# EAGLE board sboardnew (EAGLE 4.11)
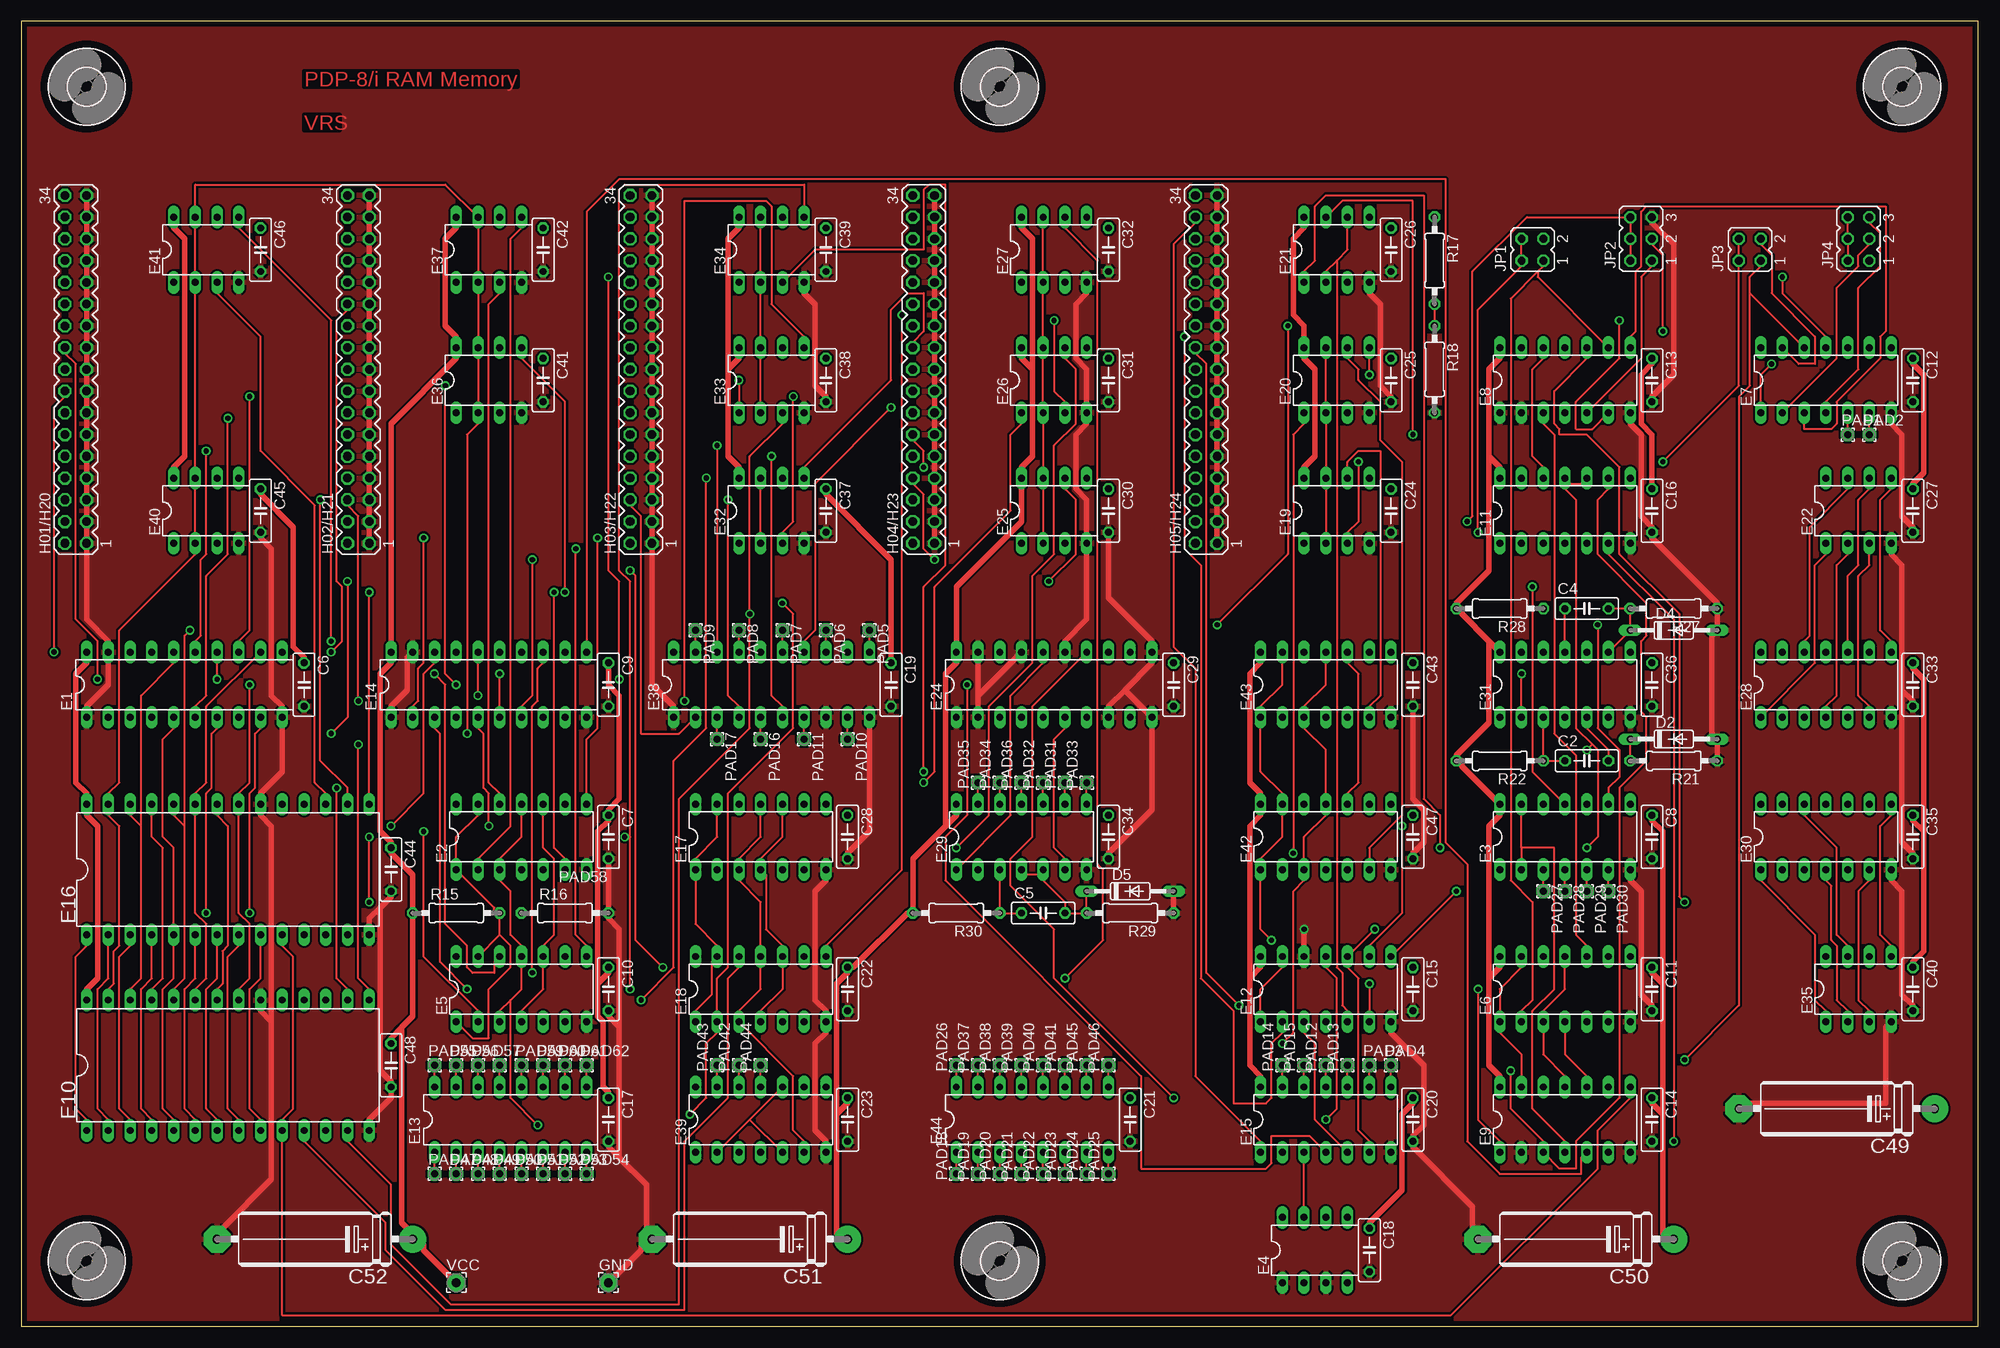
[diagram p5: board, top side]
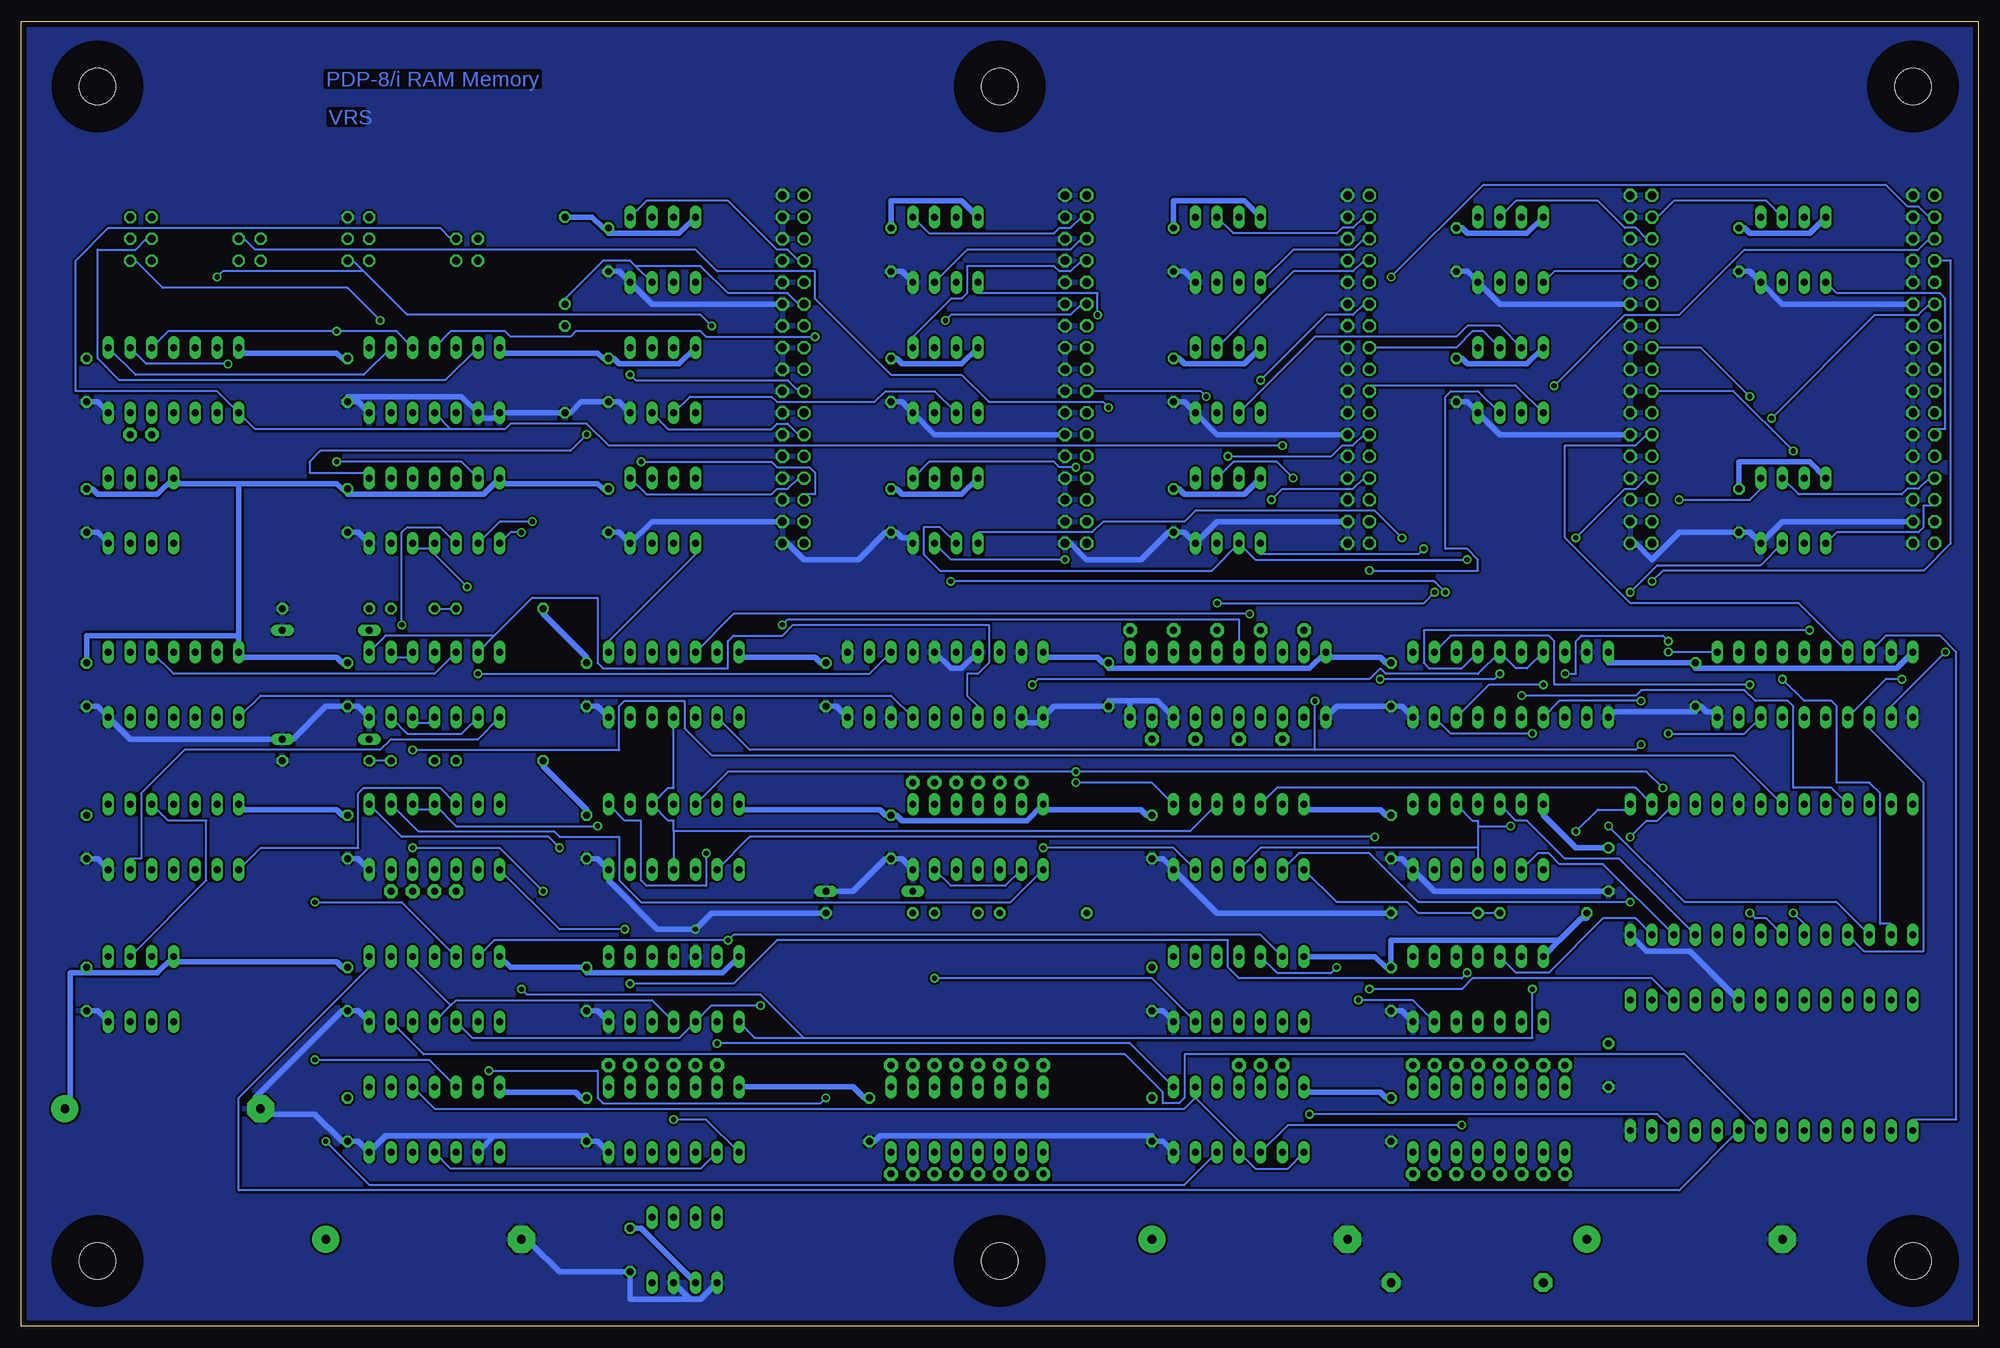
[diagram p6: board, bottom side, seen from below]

Size 228.6 x 152.4 mm. Coordinates in mm from the lower left corner, seen from the top.
Outline: 0,0 228.6,0 228.6,152.4 0,152.4 0,0
Copper layers (1*16): Top 0.035mm / dielectric 1.5mm / Bottom 0.035mm
Design rules "olimex10mil": minimum track width 10mil, minimum drill 24mil, track to track 10mil, track to pad 10mil, pad to pad 10mil, via to via 10mil, smd to smd 10mil, copper to edge 25mil, drill to drill 10mil, minimum pad ring 10mil, minimum via ring 8mil, stop-mask expansion 0mil, vias tented up to drill 0mil, thermal gap 10mil
Net classes: 1 Power: width 0.635 mm

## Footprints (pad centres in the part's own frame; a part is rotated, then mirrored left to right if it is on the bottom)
C050-025X075 = drill 0.813 octagon: 1 -2.54,0; 2 2.54,0
E22-6 = drill 1.016 pad 3.15 round: + -11.43,0 | drill 1.016 pad 3.15 octagon: - 11.43,0
DO35-10 = drill 0.813 long: A 5.08,0; C -5.08,0
DIL20 = drill 0.813 long: 1 -11.43,-3.81; 2 -8.89,-3.81; 3 -6.35,-3.81; 4 -3.81,-3.81; 5 -1.27,-3.81; 6 1.27,-3.81; 7 3.81,-3.81; 8 6.35,-3.81; 9 8.89,-3.81; 10 11.43,-3.81; 11 11.43,3.81; 12 8.89,3.81; 13 6.35,3.81; 14 3.81,3.81; 15 1.27,3.81; 16 -1.27,3.81; 17 -3.81,3.81; 18 -6.35,3.81; 19 -8.89,3.81; 20 -11.43,3.81
DIL14 = drill 0.813 long: 1 -7.62,-3.81; 2 -5.08,-3.81; 3 -2.54,-3.81; 4 0,-3.81; 5 2.54,-3.81; 6 5.08,-3.81; 7 7.62,-3.81; 8 7.62,3.81; 9 5.08,3.81; 10 2.54,3.81; 11 0,3.81; 12 -2.54,3.81; 13 -5.08,3.81; 14 -7.62,3.81
DIL08 = drill 0.813 long: 1 -3.81,-3.81; 2 -1.27,-3.81; 3 1.27,-3.81; 4 3.81,-3.81; 5 3.81,3.81; 6 1.27,3.81; 7 -1.27,3.81; 8 -3.81,3.81
DIL28-6 = drill 0.813 long: 1 -16.51,-7.62; 2 -13.97,-7.62; 3 -11.43,-7.62; 4 -8.89,-7.62; 5 -6.35,-7.62; 6 -3.81,-7.62; 7 -1.27,-7.62; 8 1.27,-7.62; 9 3.81,-7.62; 10 6.35,-7.62; 11 8.89,-7.62; 12 11.43,-7.62; 13 13.97,-7.62; 14 16.51,-7.62; 15 16.51,7.62; 16 13.97,7.62; 17 11.43,7.62; 18 8.89,7.62; 19 6.35,7.62; 20 3.81,7.62; 21 1.27,7.62; 22 -1.27,7.62; 23 -3.81,7.62; 24 -6.35,7.62; 25 -8.89,7.62; 26 -11.43,7.62; 27 -13.97,7.62; 28 -16.51,7.62
DIL16 = drill 0.813 long: 1 -8.89,-3.81; 2 -6.35,-3.81; 3 -3.81,-3.81; 4 -1.27,-3.81; 5 1.27,-3.81; 6 3.81,-3.81; 7 6.35,-3.81; 8 8.89,-3.81; 9 8.89,3.81; 10 6.35,3.81; 11 3.81,3.81; 12 1.27,3.81; 13 -1.27,3.81; 14 -3.81,3.81; 15 -6.35,3.81; 16 -8.89,3.81
2,15/1,0 = drill 1.016 pad 2.159 octagon: 1 0,0
MA17-2 = drill 1.016 octagon: 1 -20.32,-1.27; 2 -20.32,1.27; 3 -17.78,-1.27; 4 -17.78,1.27; 5 -15.24,-1.27; 6 -15.24,1.27; 7 -12.7,-1.27; 8 -12.7,1.27; 9 -10.16,-1.27; 10 -10.16,1.27; 11 -7.62,-1.27; 12 -7.62,1.27; 13 -5.08,-1.27; 14 -5.08,1.27; 15 -2.54,-1.27; 16 -2.54,1.27; 17 0,-1.27; 18 0,1.27; 19 2.54,-1.27; 20 2.54,1.27; 21 5.08,-1.27; 22 5.08,1.27; 23 7.62,-1.27; 24 7.62,1.27; 25 10.16,-1.27; 26 10.16,1.27; 27 12.7,-1.27; 28 12.7,1.27; 29 15.24,-1.27; 30 15.24,1.27; 31 17.78,-1.27; 32 17.78,1.27; 33 20.32,-1.27; 34 20.32,1.27
JP2Q = drill 0.914 octagon: 1 -1.27,-1.27; 2 -1.27,1.27; 3 1.27,-1.27; 4 1.27,1.27
JP3Q = drill 0.914 octagon: 1 -2.54,-1.27; 2 -2.54,1.27; 3 0,-1.27; 4 0,1.27; 5 2.54,-1.27; 6 2.54,1.27
1,6/0,8 = drill 0.813 pad 1.6 octagon: 1 0,0
0207/10 = drill 0.813 octagon: 1 -5.08,0; 2 5.08,0
4,3 = hole 4.3: 0,0

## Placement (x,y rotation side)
C2  .22uf  [C050-025X075]  182.88,66.04 0 top
C4  .22uf  [C050-025X075]  182.88,83.82 0 top
C5  .22uf  [C050-025X075]  119.38,48.26 0 top
C6  [C050-025X075]  33.02,74.93 270 top
C7  [C050-025X075]  68.58,57.15 270 top
C8  [C050-025X075]  190.5,57.15 270 top
C9  [C050-025X075]  68.58,74.93 270 top
C10  [C050-025X075]  68.58,39.37 270 top
C11  [C050-025X075]  190.5,39.37 270 top
C12  [C050-025X075]  220.98,110.49 270 top
C13  [C050-025X075]  190.5,110.49 270 top
C14  [C050-025X075]  190.5,24.13 270 top
C15  [C050-025X075]  162.56,39.37 270 top
C16  [C050-025X075]  190.5,95.25 270 top
C17  [C050-025X075]  68.58,24.13 270 top
C18  [C050-025X075]  157.48,8.89 270 top
C19  [C050-025X075]  101.6,74.93 270 top
C20  [C050-025X075]  162.56,24.13 270 top
C21  [C050-025X075]  129.54,24.13 270 top
C22  [C050-025X075]  96.52,39.37 270 top
C23  [C050-025X075]  96.52,24.13 270 top
C24  [C050-025X075]  160.02,95.25 270 top
C25  [C050-025X075]  160.02,110.49 270 top
C26  [C050-025X075]  160.02,125.73 270 top
C27  [C050-025X075]  220.98,95.25 270 top
C28  [C050-025X075]  96.52,57.15 270 top
C29  [C050-025X075]  134.62,74.93 270 top
C30  [C050-025X075]  127,95.25 270 top
C31  [C050-025X075]  127,110.49 270 top
C32  [C050-025X075]  127,125.73 270 top
C33  [C050-025X075]  220.98,74.93 270 top
C34  [C050-025X075]  127,57.15 270 top
C35  [C050-025X075]  220.98,57.15 270 top
C36  [C050-025X075]  190.5,74.93 270 top
C37  [C050-025X075]  93.98,95.25 270 top
C38  [C050-025X075]  93.98,110.49 270 top
C39  [C050-025X075]  93.98,125.73 270 top
C40  [C050-025X075]  220.98,39.37 270 top
C41  [C050-025X075]  60.96,110.49 270 top
C42  [C050-025X075]  60.96,125.73 270 top
C43  [C050-025X075]  162.56,74.93 270 top
C44  [C050-025X075]  43.18,53.34 270 top
C45  [C050-025X075]  27.94,95.25 270 top
C46  [C050-025X075]  27.94,125.73 270 top
C47  [C050-025X075]  162.56,57.15 270 top
C48  [C050-025X075]  43.18,30.48 270 top
C49  [E22-6]  212.09,25.4 180 top
C50  [E22-6]  181.61,10.16 180 top
C51  [E22-6]  85.09,10.16 180 top
C52  [E22-6]  34.29,10.16 180 top
D2  1N4148  [DO35-10]  193.04,68.58 0 top
D4  1N4148  [DO35-10]  193.04,81.28 0 top
D5  1N4148  [DO35-10]  129.54,50.8 0 top
E1  74S240N  [DIL20]  19.05,74.93 0 top
E2  74S74N  [DIL14]  58.42,57.15 0 top
E3  7410N  [DIL14]  180.34,57.15 0 top
E4  MAX702CPA  [DIL08]  151.13,8.89 0 top
E5  74S74N  [DIL14]  58.42,39.37 0 top
E6  74S74N  [DIL14]  180.34,39.37 0 top
E7  7404N  [DIL14]  210.82,110.49 0 top
E8  7400N  [DIL14]  180.34,110.49 0 top
E9  74S74N  [DIL14]  180.34,24.13 0 top
E10  [DIL28-6]  24.13,30.48 0 top
E11  7410N  [DIL14]  180.34,95.25 0 top
E12  74S74N  [DIL14]  152.4,39.37 0 top
E13  [DIL16]  57.15,24.13 0 top
E14  74S240N  [DIL20]  54.61,74.93 0 top
E15  7404N  [DIL14]  152.4,24.13 0 top
E16  [DIL28-6]  24.13,53.34 0 top
E17  74S74N  [DIL14]  86.36,57.15 0 top
E18  74S74N  [DIL14]  86.36,39.37 0 top
E19  DS75453N  [DIL08]  153.67,95.25 0 top
E20  DS75453N  [DIL08]  153.67,110.49 0 top
E21  DS75453N  [DIL08]  153.67,125.73 0 top
E22  DS1100M-250  [DIL08]  214.63,95.25 0 top
E24  74S240N  [DIL20]  120.65,74.93 0 top
E25  DS75453N  [DIL08]  120.65,95.25 0 top
E26  DS75453N  [DIL08]  120.65,110.49 0 top
E27  DS75453N  [DIL08]  120.65,125.73 0 top
E28  DS1005-250  [DIL14]  210.82,74.93 0 top
E29  7400N  [DIL14]  116.84,57.15 0 top
E30  DS1005-250  [DIL14]  210.82,57.15 0 top
E31  7400N  [DIL14]  180.34,74.93 0 top
E32  DS75453N  [DIL08]  87.63,95.25 0 top
E33  DS75453N  [DIL08]  87.63,110.49 0 top
E34  DS75453N  [DIL08]  87.63,125.73 0 top
E35  DS1100M-250  [DIL08]  214.63,39.37 0 top
E36  DS75453N  [DIL08]  54.61,110.49 0 top
E37  DS75453N  [DIL08]  54.61,125.73 0 top
E38  74S240N  [DIL20]  87.63,74.93 0 top
E39  7400N  [DIL14]  86.36,24.13 0 top
E40  DS75453N  [DIL08]  21.59,95.25 0 top
E41  DS75453N  [DIL08]  21.59,125.73 0 top
E42  74S74N  [DIL14]  152.4,57.15 0 top
E43  74S74N  [DIL14]  152.4,74.93 0 top
E44  [DIL16]  118.11,24.13 0 top
GND  [2,15/1,0]  68.58,5.08 0 top
H01/H20  [MA17-2]  6.35,111.76 90 top
H02/H21  [MA17-2]  39.37,111.76 90 top
H03/H22  [MA17-2]  72.39,111.76 90 top
H04/H23  [MA17-2]  105.41,111.76 90 top
H05/H24  [MA17-2]  138.43,111.76 90 top
JP1  [JP2Q]  176.53,125.73 90 top
JP2  [JP3Q]  189.23,127 90 top
JP3  [JP2Q]  201.93,125.73 90 top
JP4  [JP3Q]  214.63,127 90 top
PAD1  [1,6/0,8]  213.36,104.14 0 top
PAD2  [1,6/0,8]  215.9,104.14 0 top
PAD3  [1,6/0,8]  157.48,30.48 0 top
PAD4  [1,6/0,8]  160.02,30.48 0 top
PAD5  [1,6/0,8]  99.06,81.28 270 top
PAD6  [1,6/0,8]  93.98,81.28 270 top
PAD7  [1,6/0,8]  88.9,81.28 270 top
PAD8  [1,6/0,8]  83.82,81.28 270 top
PAD9  [1,6/0,8]  78.74,81.28 270 top
PAD10  [1,6/0,8]  96.52,68.58 270 top
PAD11  [1,6/0,8]  91.44,68.58 270 top
PAD12  [1,6/0,8]  152.4,30.48 90 top
PAD13  [1,6/0,8]  154.94,30.48 90 top
PAD14  [1,6/0,8]  147.32,30.48 90 top
PAD15  [1,6/0,8]  149.86,30.48 90 top
PAD16  [1,6/0,8]  86.36,68.58 270 top
PAD17  [1,6/0,8]  81.28,68.58 270 top
PAD18  [1,6/0,8]  109.22,17.78 90 top
PAD19  [1,6/0,8]  111.76,17.78 90 top
PAD20  [1,6/0,8]  114.3,17.78 90 top
PAD21  [1,6/0,8]  116.84,17.78 90 top
PAD22  [1,6/0,8]  119.38,17.78 90 top
PAD23  [1,6/0,8]  121.92,17.78 90 top
PAD24  [1,6/0,8]  124.46,17.78 90 top
PAD25  [1,6/0,8]  127,17.78 90 top
PAD26  [1,6/0,8]  109.22,30.48 90 top
PAD27  [1,6/0,8]  177.8,50.8 270 top
PAD28  [1,6/0,8]  180.34,50.8 270 top
PAD29  [1,6/0,8]  182.88,50.8 270 top
PAD30  [1,6/0,8]  185.42,50.8 270 top
PAD31  [1,6/0,8]  121.92,63.5 90 top
PAD32  [1,6/0,8]  119.38,63.5 90 top
PAD33  [1,6/0,8]  124.46,63.5 90 top
PAD34  [1,6/0,8]  114.3,63.5 90 top
PAD35  [1,6/0,8]  111.76,63.5 90 top
PAD36  [1,6/0,8]  116.84,63.5 90 top
PAD37  [1,6/0,8]  111.76,30.48 90 top
PAD38  [1,6/0,8]  114.3,30.48 90 top
PAD39  [1,6/0,8]  116.84,30.48 90 top
PAD40  [1,6/0,8]  119.38,30.48 90 top
PAD41  [1,6/0,8]  121.92,30.48 90 top
PAD42  [1,6/0,8]  83.82,30.48 90 top
PAD43  [1,6/0,8]  81.28,30.48 90 top
PAD44  [1,6/0,8]  86.36,30.48 90 top
PAD45  [1,6/0,8]  124.46,30.48 90 top
PAD46  [1,6/0,8]  127,30.48 90 top
PAD47  [1,6/0,8]  48.26,17.78 0 top
PAD48  [1,6/0,8]  50.8,17.78 0 top
PAD49  [1,6/0,8]  53.34,17.78 0 top
PAD50  [1,6/0,8]  55.88,17.78 0 top
PAD51  [1,6/0,8]  58.42,17.78 0 top
PAD52  [1,6/0,8]  60.96,17.78 0 top
PAD53  [1,6/0,8]  63.5,17.78 0 top
PAD54  [1,6/0,8]  66.04,17.78 0 top
PAD55  [1,6/0,8]  48.26,30.48 0 top
PAD56  [1,6/0,8]  50.8,30.48 0 top
PAD57  [1,6/0,8]  53.34,30.48 0 top
PAD58  [1,6/0,8]  55.88,30.48 0 top
PAD59  [1,6/0,8]  58.42,30.48 0 top
PAD60  [1,6/0,8]  60.96,30.48 0 top
PAD61  [1,6/0,8]  63.5,30.48 0 top
PAD62  [1,6/0,8]  66.04,30.48 0 top
R15  330  [0207/10]  50.8,48.26 0 top
R16  750  [0207/10]  63.5,48.26 0 top
R17  330  [0207/10]  165.1,124.46 270 top
R18  750  [0207/10]  165.1,111.76 270 top
R21  330  [0207/10]  193.04,66.04 180 top
R22  330  [0207/10]  172.72,66.04 180 top
R27  330  [0207/10]  193.04,83.82 180 top
R28  330  [0207/10]  172.72,83.82 180 top
R29  330  [0207/10]  129.54,48.26 180 top
R30  330  [0207/10]  109.22,48.26 180 top
U$20  [4,3]  219.71,144.78 270 top
U$66  [4,3]  114.3,144.78 270 top
U$67  [4,3]  114.3,7.62 270 top
U$82  [4,3]  219.71,7.62 270 top
U$83  [4,3]  7.62,7.62 270 top
U$86  [4,3]  7.62,144.78 270 top
VCC  [2,15/1,0]  50.8,5.08 0 top

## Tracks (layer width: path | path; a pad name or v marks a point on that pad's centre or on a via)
B17S1
  Top 0.254: E9.10 182.88,29.21 180.34,31.75 E6.4 | E8.3 177.8,105.41 179.07,104.14 179.07,69.22 181.61,66.67 181.61,45.72 182.88,44.45 E6.10
  Bottom 0.254: E39.1 80.64,18.41 84.45,18.41 E39.4 86.36,21.59 91.44,26.67 | 178.44,37.47 177.8,38.1 154.94,38.1 E12.4 | 178.44,37.47 E6.4 | 178.44,37.47 182.88,41.91 E6.10 | 91.44,26.67 92.71,25.4 180.34,25.4 E9.10 | 91.44,26.67 E39.9
B17V1  (via drill 0.61)
  Top 0.254: E18.1 78.74,36.83 80.64,38.73 80.64,42.55 E18.13 81.28,44.45 78.74,46.99 E17.1 78.74,54.61 81.28,57.15 E17.13 | 55.88,45.72 57.15,44.45 57.15,41.91 54.61,39.37 54.61,33.66 52.7,33.66 E5.1 | 55.88,45.72 R15.2 55.24,48.26 55.24,48.9 E2.1 50.8,57.15 53.34,59.69 E2.13 | 55.88,45.72 E5.13 | E9.13 175.26,31.75 172.72,34.29 E6.1 172.72,39.37 175.26,41.91 E6.13 | E43.13 147.32,74.93 144.78,72.39 E43.1 144.78,64.77 147.32,62.23 E42.13 147.32,57.15 144.78,54.61 E42.1 144.78,46.35 v146.05,45.09
  Bottom 0.254: R15.2 R16.1 65.41,48.26 66.67,49.53 74.93,49.53 E17.1 | E6.13 173.35,45.09 v146.05,45.09 145.41,45.72 83.82,45.72 E18.13
D01BINIT  (via drill 0.61)
  Top 0.254: v110.49,74.93 110.49,59.69 107.95,57.15 107.95,52.07 130.81,29.21 130.81,18.41 145.41,18.41 146.05,19.05 146.05,22.23 150.5,22.23 E15.4
  Bottom 0.254: E14.17 52.7,76.83 53.98,76.83 E14.15 58.42,76.2 69.22,76.2 69.85,76.83 71.12,75.56 109.86,75.56 v110.49,74.93
D01BTP2L
  Top 0.254: 175.26,55.88 E3.2 | 175.26,55.88 E3.13 | 175.26,55.88 179.07,55.88 179.07,39.37 176.53,36.83 176.53,25.4 180.34,21.59 E9.4
  Bottom 0.254: E15.2 149.22,18.41 178.44,18.41 E9.4
D01DEL2X
  Top 0.254: E22.1 210.82,90.17 209.55,88.9 209.55,77.47 E28.1
  Bottom 0.254: E24.7 127,73.66 200.66,73.66 E28.1
D01DEL4  (via drill 0.61)
  Top 0.254: E29.1 115.57,59.69 115.57,73.66 119.38,77.47 E24.16 | v184.15,81.92 184.15,69.85 186.69,67.31 186.69,64.14 185.42,62.87 E3.9
  Bottom 0.254: v184.15,81.92 184.15,92.71 183.51,93.34 179.71,93.34 E11.3 | E29.1 113.03,49.53 156.21,49.53 158.75,52.07 158.75,57.15 165.74,57.15 166.37,57.78 182.25,57.78 E3.9
D01DEL5  (via drill 0.61)
  Top 0.254: E11.9 185.42,97.79 184.15,96.52 184.15,90.17 189.87,84.45 189.87,80.64 189.23,80.01 189.23,71.75 189.87,71.12 189.87,66.04 186.69,62.87 186.69,26.67 181.61,21.59 181.61,18.41 179.71,18.41 E9.3 177.8,21.59 173.99,25.4 v173.99,29.84 | v134.62,26.67 120.65,40.64 120.65,46.35 115.57,51.44 115.57,54.61 118.11,57.15 118.11,72.39 E24.14
  Bottom 0.254: v134.62,26.67 135.25,26.04 160.66,26.04 161.29,26.67 161.29,29.84 v173.99,29.84
D01DONEL  (via drill 0.61)
  Top 0.254: v162.56,104.14 162.56,131.44 154.31,131.44 E21.7
  Bottom 0.254: v162.56,104.14 164.47,102.23 193.68,102.23 194.94,100.97 194.94,99.69 188.59,99.69 E11.8
D01INITL  (via drill 0.61)
  Top 0.254: v52.07,39.37 48.9,42.55 48.9,69.22 48.26,69.85 E14.3 | E12.13 147.32,41.91 144.78,39.37 E12.1 | v170.18,39.37 170.18,24.13 172.72,21.59 E9.1
  Bottom 0.254: v52.07,39.37 52.07,33.66 137.16,33.66 | 137.16,33.66 142.88,33.66 E12.1 | v170.18,39.37 169.54,38.73 142.24,38.73 137.16,33.66
D01LOADMDL  (via drill 0.61)
  Top 0.254: 85.09,24.13 E39.2 | 85.09,24.13 E39.10 | E39.5 85.09,24.13 | v193.04,21.59 193.04,82.55 185.42,90.17 E11.6
  Bottom 0.254: v193.04,21.59 187.96,16.51 92.71,16.51 E39.5
D01MEMDONEL
  Bottom 0.254: E21.5 155.57,131.44 146.05,131.44 140.34,125.73 139.06,125.73 137.79,124.46 H05/H24.28
D01MEMSTARTL  (via drill 0.61)
  Top 0.254: E15.6 157.48,21.59 156.21,22.86 156.21,40.64 154.94,41.91 E12.10 v158.12,46.35
  Bottom 0.254: v158.12,46.35 165.74,46.35 E3.1
D01POWEROK
  Top 0.254: E4.7 E15.3
D01READH  (via drill 0.61)
  Top 0.254: v161.29,58.42 161.29,48.26 157.48,44.45 E12.9 | v176.53,86.36 176.53,64.77 E3.11
  Bottom 0.254: E11.5 182.25,90.81 180.97,90.81 E11.4 180.34,90.17 v176.53,86.36 | v161.29,58.42 177.8,58.42 E3.11 180.97,60.33 182.25,60.33 E3.10
D01READL  (via drill 0.61)
  Top 0.254: E10.22 22.86,39.37 23.5,40.01 23.5,43.81 24.13,44.45 24.13,58.42 22.86,59.69 E16.22 | v182.88,55.88 184.15,57.15 184.15,67.31 183.51,67.94 | 183.51,67.94 181.61,69.85 181.61,96.52 180.34,97.79 E11.11 180.97,98.42 182.25,98.42 E11.10 | v167.64,50.8 E12.8 | 183.51,67.94 v182.88,67.31
  Bottom 0.254: v167.64,50.8 172.72,55.88 v182.88,55.88 | v182.88,67.31 158.75,67.31 158.75,72.39 158.12,73.03 151.13,73.03 151.13,69.85 147.96,66.67 28.57,66.67 E16.22
D01SELECTH  (via drill 0.61)
  Top 0.254: v59.69,41.27 59.69,72.39 60.33,73.03 60.33,76.83 60.96,77.47 E14.13 | v157.48,40.01 E12.6
  Bottom 0.254: v59.69,41.27 60.33,40.64 86.36,40.64 87.63,41.91 87.63,45.09 140.34,45.09 145.41,40.01 v157.48,40.01
D01SELECTL
  Top 0.254: 153.67,124.46 154.94,125.73 E21.6 | 153.67,124.46 152.4,123.19 E21.2 | 153.67,124.46 153.67,41.91 154.31,41.27 154.31,37.47 154.94,36.83 E12.5
D01SELL  (via drill 0.61)
  Top 0.254: v135.89,115.57 135.89,90.81 137.79,88.9 137.79,40.64 141.6,36.83 141.6,26.04 145.41,26.04 146.05,26.67 146.05,33.02 147.32,34.29 E12.2
  Bottom 0.254: v135.89,115.57 148.59,115.57 149.22,116.2 163.83,116.2 164.47,115.57 171.45,115.57 172.09,116.2 178.44,116.2 E8.11
D01STROBEL
  Top 0.254: R17.2 R18.1
  Bottom 0.254: 156.84,123.83 157.48,124.46 160.66,124.46 165.1,120.02 R17.2 | 156.84,123.83 E21.3 | 156.84,123.83 149.22,123.83 146.05,120.65 139.06,120.65 137.79,119.38 H05/H24.24
D01WRITEH
  Top 0.254: E14.11 66.04,130.18 69.85,133.99 166.37,133.99 166.37,56.52 168.91,53.98 168.91,21.59 172.72,17.78 182.25,17.78 182.25,19.68 E9.5
D01WRITEL  (via drill 0.61)
  Top 0.254: E33.2 E33.7 E34.2 E34.7 | v52.07,69.22 52.07,104.14 53.34,105.41 E36.2 E36.7 E37.2 E37.7 49.53,133.35 20.32,133.35 E41.7 E41.2 E40.7 E40.2 20.32,90.17 11.43,81.28 11.43,63.5 10.16,62.23 E16.27 10.16,59.69 11.43,58.42 11.43,44.45 10.79,43.81 10.79,40.01 10.16,39.37 E10.27
  Bottom 0.254: v52.07,69.22 61.59,69.22 E14.9 | E33.2 77.47,115.57 60.96,115.57 59.69,116.84 55.88,116.84 E36.7
D02MEM0  (via drill 0.61)
  Top 0.254: v106.68,89.53 105.41,90.81 105.41,97.16 104.14,98.42 H04/H23.8
  Bottom 0.254: v106.68,89.53 120.02,89.53 E25.3
D02MEM1  (via drill 0.61)
  Top 0.254: v105.41,100.33 105.41,102.23 104.14,103.5 H04/H23.12
  Bottom 0.254: v105.41,100.33 107.31,100.33 107.95,100.97 122.56,100.97 E25.5
D02MEM2  (via drill 0.61)
  Top 0.254: v90.17,108.58 90.17,93.98 88.9,92.71 E32.3
  Bottom 0.254: v90.17,108.58 90.81,109.22 H04/H23.16
D02MEM3
  Top 0.254: E32.5 91.44,100.33 101.6,110.49 101.6,118.75 103.5,120.65 105.41,120.65 105.41,116.2 104.14,114.94 H04/H23.20
D02MEM4  (via drill 0.61)
  Top 0.254: v120.65,117.47 120.65,109.22 121.92,107.95 E26.3
  Bottom 0.254: v120.65,117.47 120.02,118.11 106.05,118.11 104.78,119.38 H04/H23.24
D02MEM5
  Bottom 0.254: E26.5 124.46,115.57 120.02,120.02 118.75,120.02 118.11,120.65 118.11,123.83 107.95,123.83 107.31,123.19 106.05,123.19 104.78,124.46 H04/H23.28
D02MEM6
  Bottom 0.254: E27.3 118.11,125.73 106.05,125.73 104.78,127 H04/H23.30
D02MEM7
  Bottom 0.254: E27.5 122.56,127.64 107.95,127.64 107.31,128.27 106.05,128.27 104.78,129.54 H04/H23.32
D02MEM8  (via drill 0.61)
  Top 0.254: v156.21,100.97 156.21,93.98 154.94,92.71 E19.3
  Bottom 0.254: v156.21,100.97 140.97,100.97 140.34,100.33 136.53,100.33 135.89,99.69 135.89,97.16 137.16,97.16 H05/H24.6
D02MEM9
  Bottom 0.254: E19.5 155.57,97.16 140.97,97.16 140.34,97.79 139.06,97.79 137.79,99.06 H05/H24.8
D02MEM10
  Bottom 0.254: E20.3 153.03,104.78 140.97,104.78 140.34,105.41 139.06,105.41 137.79,104.14 H05/H24.12
D02MEM11  (via drill 0.61)
  Top 0.254: v157.48,111.12 E20.5
  Bottom 0.254: v157.48,111.12 156.84,110.49 139.06,110.49 137.79,109.22 H05/H24.16
D03BEMA0L
  Top 0.254: E10.8 25.4,24.13 24.13,25.4 24.13,43.18 25.4,44.45 E16.8
  Bottom 0.254: E6.6 181.61,31.75 99.69,31.75 95.25,27.3 95.25,26.04 93.34,26.04 92.71,26.67 92.71,31.75 34.29,31.75 E10.8
D03BEMA1L
  Top 0.254: E10.9 27.94,24.13 26.67,25.4 26.67,39.37 27.94,40.64 E16.9
  Bottom 0.254: E6.8 187.96,41.91 203.2,26.67 203.2,15.88 34.92,15.88 E10.9
D03BEMA2L
  Top 0.254: E16.10 30.48,44.45 31.75,43.18 31.75,25.4 30.48,24.13 E10.10 30.48,1.27 167,1.27 184.15,18.41 184.15,22.86 187.96,26.67 E9.8
D03BMA0  (via drill 0.61)
  Top 0.254: v3.81,78.74 3.81,107.31 5.08,108.58 H01/H20.16
  Bottom 0.254: v3.81,78.74 10.16,72.39 E1.2
D03BMA1  (via drill 0.61)
  Top 0.254: v8.89,75.56 8.89,80.01 6.35,82.55 6.35,112.39 5.08,113.67 H01/H20.20
  Bottom 0.254: v8.89,75.56 10.79,75.56 E1.4
D03BMA2  (via drill 0.61)
  Top 0.254: v24.13,106.05 24.13,90.17 21.59,87.63 21.59,73.66 20.32,72.39 E1.6
  Bottom 0.254: v24.13,106.05 12.06,118.11 6.99,118.11 5.71,119.38 H01/H20.24
D03BMA3  (via drill 0.61)
  Top 0.254: v36.2,69.22 38.1,71.12 v38.1,87
  Bottom 0.254: v36.2,69.22 27.3,69.22 E1.8 | v38.1,87 36.83,88.27 6.35,88.27 3.17,91.44 3.17,124.46 H01/H20.28
D03BMA4  (via drill 0.61)
  Top 0.254: v50.8,74.93 49.53,76.2 v49.53,109.86
  Bottom 0.254: v50.8,74.93 57.15,74.93 E14.8 | v49.53,109.86 41.27,118.11 34.92,118.11 27.3,125.73 6.99,125.73 5.71,127 H01/H20.30
D03BMA5  (via drill 0.61)
  Top 0.254: v69.85,75.56 69.85,87 68.58,88.27 v68.58,122.56 | E14.6 v55.88,76.2
  Bottom 0.254: v55.88,76.2 56.52,75.56 v69.85,75.56 | v68.58,122.56 57.78,133.35 10.79,133.35 8.26,130.81 6.99,130.81 5.71,129.54 H01/H20.32
D03BMA6  (via drill 0.61)
  Top 0.254: v39.37,73.03 39.37,94.61 38.1,95.89 H02/H21.6
  Bottom 0.254: v39.37,73.03 48.9,73.03 E14.4
D03BMA7  (via drill 0.61)
  Top 0.254: v46.99,92.08 46.99,77.47 46.35,76.83 46.35,73.03 45.72,72.39 E14.2
  Bottom 0.254: v46.99,92.08 41.27,97.79 40.01,97.79 38.73,99.06 H02/H21.8
D03BMA8
  Bottom 0.254: E1.17 20.95,84.45 40.64,84.45 48.26,92.08 48.26,102.87 40.01,102.87 38.73,104.14 H02/H21.12
D03BMA9  (via drill 0.61)
  Top 0.254: v21.59,102.23 21.59,90.17 20.95,89.53 20.95,80.64 20.32,80.01 E1.15
  Bottom 0.254: v21.59,102.23 28.57,109.22 H02/H21.16
D03BMA10  (via drill 0.61)
  Top 0.254: v26.67,108.58 26.67,81.28 25.4,80.01 E1.13
  Bottom 0.254: v26.67,108.58 32.38,114.3 H02/H21.20
D03BMA11  (via drill 0.61)
  Top 0.254: v36.2,78.74 37.47,80.01 37.47,86.36 36.83,87 36.83,117.47 38.1,118.75 H02/H21.24
  Bottom 0.254: E1.11 v36.2,78.74
D03BTP2  (via drill 0.61)
  Top 0.254: v152.4,24.13 153.67,25.4 153.67,40.64 152.4,41.91 E12.11 | H05/H24.32 137.16,128.91 134.62,126.36 134.62,79.38 137.16,76.83 137.16,29.21 144.78,21.59 E15.1
  Bottom 0.254: v152.4,24.13 148.59,24.13 E15.1
D03EA0
  Top 0.254: E38.2 76.83,69.22 72.39,69.22 72.39,94.61 71.12,95.89 H03/H22.6
D03EA1  (via drill 0.61)
  Top 0.254: v82.55,96.52 82.55,73.66 83.82,72.39 E38.4
  Bottom 0.254: v82.55,96.52 81.28,97.79 73.03,97.79 71.75,99.06 H03/H22.8
D03EA2  (via drill 0.61)
  Top 0.254: v87.63,101.6 87.63,73.66 88.9,72.39 E38.6
  Bottom 0.254: v87.63,101.6 75.56,101.6 74.3,102.87 73.03,102.87 71.75,104.14 H03/H22.12
D03EMA0H
  Top 0.254: 177.16,123.19 177.8,123.83 JP1.1 | 177.16,123.19 173.99,120.02 173.99,52.07 176.53,49.53 176.53,38.1 175.26,36.83 E6.2 | 177.16,123.19 177.16,122.56 E8.9
  Bottom 0.254: E7.8 215.26,111.12 188.59,111.12 E8.9
D03EMA0L  (via drill 0.61)
  Top 0.254: v81.28,102.87 E38.18 | v204.47,112.39 203.2,111.12 E7.1
  Bottom 0.254: v81.28,102.87 160.02,102.87 162.56,105.41 171.45,105.41 172.09,104.78 178.44,104.78 | 178.44,104.78 E8.4 | 178.44,104.78 201.29,104.78 E7.1 205.74,109.22 222.25,109.22 222.25,124.46 218.44,128.27 179.71,128.27 178.44,127 JP1.3 | v204.47,112.39 214,112.39 E7.9
D03EMA1H  (via drill 0.61)
  Top 0.254: v194.31,49.53 193.68,50.16 193.68,83.19 186.69,90.17 186.69,100.33 182.88,104.14 179.71,104.14 179.71,104.78 179.07,105.41 179.07,109.22 182.88,113.03 E8.10 | v191.77,116.2 191.77,125.09 190.5,126.36 JP2.3
  Bottom 0.254: v194.31,49.53 184.15,49.53 E6.12 | E7.10 211.46,116.2 v191.77,116.2 184.78,116.2 E8.10
D03EMA1L  (via drill 0.61)
  Top 0.254: v139.7,81.92 147.96,90.17 v147.96,116.84 | E8.5 189.23,113.03 189.23,122.56 190.5,123.83 JP2.1 | v205.74,122.56 205.74,120.65 210.82,115.57 E7.11
  Bottom 0.254: v139.7,81.92 139.06,82.55 86.36,82.55 E38.16 | v147.96,116.84 149.22,118.11 183.51,118.11 188.59,123.19 | 188.59,123.19 189.87,124.46 JP2.1 | v205.74,122.56 205.1,123.19 188.59,123.19
D03EMA2H  (via drill 0.61)
  Top 0.254: v194.31,31.11 200.66,37.47 200.66,108.58 201.93,109.86 201.93,120.65 | 201.93,120.65 201.93,122.56 203.2,123.83 JP3.1 | 201.93,120.65 E7.12
  Bottom 0.254: v194.31,31.11 180.97,31.11 E9.12
D03EMA2L  (via drill 0.61)
  Top 0.254: v101.6,107.31 92.71,98.42 92.71,81.28 91.44,80.01 E38.14 | E7.13 207.65,112.39 209.55,112.39 209.55,115.57 204.47,120.65 204.47,125.09 203.2,126.36 JP3.3
  Bottom 0.254: v101.6,107.31 102.23,107.95 115.57,107.95 118.75,111.12 127,111.12 135.89,120.02 135.89,123.19 147.32,123.19 149.86,125.73 201.29,125.73 202.56,127 JP3.3
D03MA0L
  Top 0.254: E10.1 7.62,24.13 6.35,25.4 6.35,43.18 7.62,44.45 E16.1
  Bottom 0.254: E1.18 10.79,80.64 4.45,80.64 2.54,78.74 2.54,24.13 7.62,24.13 E10.1
D03MA1L
  Top 0.254: 13.97,58.42 13.97,40.64 12.7,39.37 E10.26 | 13.97,58.42 12.7,59.69 E16.26 | 13.97,58.42 13.97,73.66 17.78,77.47 E1.16
D03MA2L  (via drill 0.61)
  Top 0.254: E10.2 10.16,24.13 8.89,25.4 8.89,39.37 10.16,40.64 E16.2 | v22.86,75.56 E1.14
  Bottom 0.254: v22.86,75.56 20.32,73.03 17.14,73.03 16.51,72.39 16.51,63.5 12.7,63.5 11.43,62.23 11.43,46.99 10.16,46.99 E16.2
D03MA3L
  Top 0.254: E10.23 20.32,39.37 21.59,40.64 21.59,46.99 20.32,48.26 E16.23 20.32,62.23 21.59,63.5 21.59,72.39 E1.12
D03MA4L  (via drill 0.61)
  Top 0.254: E10.21 25.4,39.37 26.67,40.64 26.67,46.99 25.4,48.26 E16.21 25.4,62.23 26.67,63.5 v26.67,74.93
  Bottom 0.254: v26.67,74.93 49.53,74.93 49.53,80.01 50.16,80.64 61.59,80.64 E14.12
D03MA5L  (via drill 0.61)
  Top 0.254: 19.05,58.42 19.05,40.64 17.78,39.37 E10.24 | 19.05,58.42 17.78,59.69 E16.24 | v19.68,81.28 19.05,80.64 19.05,58.42
  Bottom 0.254: v19.68,81.28 64.77,81.28 64.77,77.47 64.14,76.83 60.33,76.83 E14.14
D03MA6L  (via drill 0.61)
  Top 0.254: E10.25 15.24,39.37 16.51,40.64 16.51,55.88 15.24,57.15 E16.25 | v53.34,73.66 E14.16
  Bottom 0.254: v53.34,73.66 40.01,73.66 39.37,74.3 27.3,74.3 26.04,73.03 22.23,73.03 21.59,72.39 21.59,62.87 17.14,62.87 E16.25
D03MA7L  (via drill 0.61)
  Top 0.254: E10.3 12.7,24.13 11.43,25.4 11.43,43.18 12.7,44.45 E16.3 | v43.18,58.42 46.99,62.23 46.99,76.2 48.26,77.47 E14.18
  Bottom 0.254: v43.18,58.42 34.29,49.53 16.51,49.53 E16.3
D03MA8L
  Top 0.254: E10.4 15.24,24.13 13.97,25.4 13.97,39.37 15.24,40.64 E16.4
  Bottom 0.254: E1.3 12.7,69.85 6.35,63.5 6.35,43.81 13.34,43.81 E16.4
D03MA9L
  Top 0.254: E10.5 17.78,24.13 16.51,25.4 16.51,39.37 17.78,40.64 E16.5 17.78,55.88 16.51,57.15 16.51,68.58 17.78,69.85 E1.5
D03MA10L  (via drill 0.61)
  Top 0.254: E10.6 20.32,24.13 19.05,25.4 19.05,39.37 20.32,40.64 E16.6 | v21.59,48.26 21.59,62.23 22.23,62.87 22.23,69.22 22.86,69.85 E1.7
  Bottom 0.254: v21.59,48.26 20.32,46.99 E16.6
D03MA11L  (via drill 0.61)
  Top 0.254: E10.7 22.86,24.13 21.59,25.4 21.59,39.37 22.86,40.64 E16.7 | v26.67,48.26 26.67,62.23 27.3,62.87 27.3,69.22 27.94,69.85 E1.9
  Bottom 0.254: v26.67,48.26 26.04,47.62 24.77,47.62 E16.7
D03MCBMB0L
  Bottom 0.254: E37.1 49.53,123.19 40.01,123.19 38.73,124.46 H02/H21.28
D03MCBMB1L
  Bottom 0.254: E37.6 53.98,131.44 44.45,131.44 41.27,128.27 40.01,128.27 38.73,127 H02/H21.30
D03MCBMB2L
  Bottom 0.254: E41.6 24.77,131.44 35.56,131.44 37.47,129.54 H02/H21.32
D03MCBMB3L
  Bottom 0.254: E40.1 16.51,92.71 6.99,92.71 6.35,93.34 6.35,95.89 5.08,95.89 H01/H20.6
D03MCBMB4L
  Bottom 0.254: E40.6 20.95,97.16 8.89,97.16 8.26,97.79 6.99,97.79 5.71,99.06 H01/H20.8
D03MCBMB5L
  Bottom 0.254: E41.1 16.51,120.65 4.45,120.65 3.81,120.02 3.81,104.78 5.08,104.78 H01/H20.12
D03MCBMB6L
  Bottom 0.254: E36.1 53.98,109.86 71.12,109.86 H03/H22.16
D03MCBMB7L
  Bottom 0.254: E36.6 57.78,116.2 59.05,116.2 60.96,114.3 H03/H22.20
D03MCBMB8L  (via drill 0.61)
  Top 0.254: v83.82,110.49 E33.1
  Bottom 0.254: v83.82,110.49 76.2,118.11 73.03,118.11 71.75,119.38 H03/H22.24
D03MCBMB9L
  Bottom 0.254: E33.6 80.01,123.19 73.03,123.19 71.75,124.46 H03/H22.28
D03MCBMB10L
  Bottom 0.254: E34.1 80.01,125.73 73.03,125.73 71.75,127 H03/H22.30
D03MCBMB11L
  Bottom 0.254: E34.6 87,127.64 74.93,127.64 74.3,128.27 73.03,128.27 71.75,129.54 H03/H22.32
D03MEMSTART  (via drill 0.61)
  Top 0.254: E6.11 180.34,39.37 177.8,36.83 E6.3 177.8,31.75 180.34,29.21 E9.11 | E15.5 151.13,24.13 151.13,33.02 149.86,34.29 E12.3 | v142.24,37.47 138.43,41.27 138.43,112.39 137.16,113.67 H05/H24.20
  Bottom 0.254: v142.24,37.47 147.96,37.47 E12.3 151.76,33.66 175.9,33.66 E6.3
D04MD0L
  Top 0.254: E37.3 55.88,120.65 54.61,119.38 54.61,63.5 55.88,62.23 E2.12
  Bottom 0.254: E16.11 41.91,54.61 48.26,54.61 52.7,59.05 53.98,59.05 E2.12
D04MD1L
  Top 0.254: E37.5 58.42,128.27 57.15,127 57.15,58.42 53.34,54.61 E2.2
  Bottom 0.254: E16.12 43.81,53.98 48.9,53.98 50.16,55.24 51.44,55.24 E2.2
D04MD2L  (via drill 0.61)
  Top 0.254: v36.2,80.01 36.2,117.47 25.4,128.27 E41.5 | v48.26,76.2 49.53,74.93 49.53,46.99 52.07,44.45 52.07,41.91 52.7,41.27 55.24,41.27 55.24,42.55 E5.12
  Bottom 0.254: E16.13 40.01,47.62 43.81,47.62 50.16,41.27 53.98,41.27 E5.12 | v36.2,80.01 36.83,80.64 46.35,80.64 46.99,80.01 46.99,76.2 v48.26,76.2
D04MD3L  (via drill 0.61)
  Top 0.254: v46.99,57.78 46.99,43.18 53.34,36.83 E5.2 | E16.15 v40.64,85.72
  Bottom 0.254: v46.99,57.78 44.45,60.33 41.27,60.33 E16.15 | v40.64,85.72 37.47,88.9 25.4,88.9 E40.3
D04MD4L  (via drill 0.61)
  Top 0.254: v34.92,96.52 34.92,66.04 38.1,62.87 E16.16
  Bottom 0.254: E16.16 40.01,62.87 81.92,62.87 E17.12 | v34.92,96.52 26.67,96.52 25.4,97.79 E40.5
D04MD5L  (via drill 0.61)
  Top 0.254: E16.17 35.56,62.23 34.29,63.5 34.29,95.89 27.94,102.23 27.94,115.57 22.86,120.65 E41.3 | v40.64,49.53 v40.64,57.15
  Bottom 0.254: v40.64,49.53 65.41,49.53 71.12,55.24 79.38,55.24 E17.2 | v40.64,57.15 38.73,59.05 37.47,59.05 E16.17
D04MD6L  (via drill 0.61)
  Top 0.254: E10.11 33.02,21.59 42.55,12.06 42.55,8.89 49.53,1.91 77.47,1.91 77.47,21.59 82.55,26.67 82.55,40.64 83.82,41.91 E18.12 | v71.12,88.27 71.75,87.63 71.75,45.09 v74.93,41.91
  Bottom 0.254: v71.12,88.27 58.42,88.27 58.42,89.53 59.69,90.81 62.23,90.81 62.23,108.58 61.59,109.22 58.42,109.22 E36.3 | v74.93,41.91 75.56,41.27 81.92,41.27 E18.12
D04MD7L  (via drill 0.61)
  Top 0.254: v78.11,24.77 80.01,26.67 80.01,33.02 81.28,34.29 E18.2 81.28,40.64 82.55,41.91 82.55,62.23 90.17,69.85 90.17,83.19 v88.9,84.45 | v63.5,85.72 63.5,107.95 58.42,113.03 E36.5
  Bottom 0.254: v78.11,24.77 37.47,24.77 E10.12 | v63.5,85.72 64.77,84.45 v88.9,84.45
D04MD8L  (via drill 0.61)
  Top 0.254: E10.13 38.1,21.59 43.18,16.51 43.18,9.53 50.16,2.54 76.83,2.54 76.83,61.59 85.09,69.85 v85.09,83.19 85.09,101.6 88.9,105.41 E33.3
  Bottom 0.254: v85.09,83.19 145.41,83.19 E43.12
D04MD9L  (via drill 0.61)
  Top 0.254: v39.37,67.94 39.37,40.64 40.64,39.37 E10.15 | v77.47,73.03 77.47,131.44 87,131.44 87.63,130.81 87.63,119.38 91.44,115.57 E33.5
  Bottom 0.254: v39.37,67.94 40.01,67.31 77.47,67.31 | 77.47,67.31 143.51,67.31 E43.2 | 77.47,67.31 v77.47,73.03
D04MD10L  (via drill 0.61)
  Top 0.254: v36.83,62.87 36.83,40.64 38.1,39.37 E10.16 | v105.41,64.77 105.41,86.36 107.95,88.9 107.95,133.35 106.05,133.35 105.41,132.72 105.41,125.73 92.71,125.73 E34.3
  Bottom 0.254: v36.83,62.87 38.73,64.77 v105.41,64.77 146.05,64.77 E42.12
D04MD11L  (via drill 0.61)
  Top 0.254: 71.12,57.15 71.12,87 69.85,88.27 69.85,132.72 70.48,133.35 91.44,133.35 E34.5 | v71.12,39.37 71.12,57.15 | 71.12,57.15 v70.48,57.15
  Bottom 0.254: v71.12,39.37 60.33,39.37 59.05,40.64 38.1,40.64 E10.17 | v70.48,57.15 143.51,57.15 E42.2
GND  (via drill 0.61)
  Top 0.635: E3.7 187.96,52.07 189.23,50.8 189.23,38.73 190.5,37.47 C11.2 | E12.7 160.02,34.29 163.83,30.48 163.83,23.5 162.56,22.23 C20.2 162.56,20.95 169.54,13.97 169.54,11.43 C50.- | JP2.5 190.5,128.91 193.04,126.36 193.04,111.12 190.5,108.58 C13.2 | H05/H24.1 H05/H24.3 H05/H24.5 H05/H24.7 H05/H24.9 H05/H24.11 H05/H24.13 H05/H24.15 H05/H24.17 H05/H24.19 H05/H24.21 H05/H24.23 H05/H24.25 H05/H24.27 H05/H24.29 H05/H24.31 H05/H24.33 | C25.2 160.02,108.58 158.75,109.86 158.75,119.38 157.48,120.65 E21.4 | C40.2 220.98,37.47 219.71,38.73 219.71,50.8 218.44,52.07 E30.7 | C27.2 220.98,93.34 219.71,94.61 219.71,104.14 218.44,105.41 E7.7 | R21.1 D2.A 197.49,69.22 197.49,80.64 D4.A R27.1 198.12,84.45 190.5,92.08 C16.2 190.5,93.34 189.23,94.61 189.23,104.14 187.96,105.41 E8.7 | 219.71,74.3 219.71,88.9 218.44,90.17 E22.4 | 219.71,74.3 220.98,73.03 C33.2 | 219.71,74.3 219.71,56.52 220.98,55.24 C35.2 | C49.- 201.93,26.04 217.81,26.04 217.81,34.92 E35.4 | H02/H21.1 H02/H21.3 H02/H21.5 H02/H21.7 H02/H21.9 H02/H21.11 H02/H21.13 H02/H21.15 H02/H21.17 H02/H21.19 H02/H21.21 H02/H21.23 H02/H21.25 H02/H21.27 H02/H21.29 H02/H21.31 H02/H21.33 | E1.1 7.62,72.39 10.16,74.93 E1.19 10.16,80.01 7.62,82.55 H01/H20.1 H01/H20.3 H01/H20.5 H01/H20.7 H01/H20.9 H01/H20.11 H01/H20.13 H01/H20.15 H01/H20.17 H01/H20.19 H01/H20.21 H01/H20.23 H01/H20.25 H01/H20.27 H01/H20.29 H01/H20.31 H01/H20.33 | C7.2 R16.2 68.58,47.62 69.85,46.35 69.85,34.92 | 69.85,19.68 73.03,16.51 73.03,11.43 C51.- 72.39,9.53 72.39,8.89 GND.1 | 69.85,19.68 68.58,20.95 C17.2 | 69.85,34.92 68.58,36.2 C10.2 | 69.85,34.92 69.85,19.68
  Top 0.635: E14.1 43.18,72.39 45.09,74.3 45.09,78.11 E14.19 | E10.14 40.64,24.13 43.18,26.67 C48.2 43.18,28.57 41.91,29.84 41.91,48.9 | 41.91,48.9 40.64,47.62 E16.14 | 41.91,48.9 43.18,50.16 C44.2 | 29.21,35.56 29.21,17.14 23.5,11.43 C52.- | 29.21,35.56 27.94,36.83 E10.20 | 29.21,35.56 29.21,58.42 27.94,59.69 E16.20 27.94,62.23 30.48,64.77 E1.10 30.48,72.39 29.21,73.66 29.21,90.81 27.94,92.08 C45.2 | H04/H23.1 H04/H23.3 H04/H23.5 H04/H23.7 H04/H23.9 H04/H23.11 H04/H23.13 H04/H23.15 H04/H23.17 H04/H23.19 H04/H23.21 H04/H23.23 H04/H23.25 H04/H23.27 H04/H23.29 H04/H23.31 H04/H23.33 | E27.4 124.46,120.65 123.19,119.38 123.19,113.03 124.46,111.76 E26.4 124.46,105.41 123.19,104.14 123.19,97.79 124.46,96.52 E25.4 124.46,82.55 121.92,80.01 E24.15 | H03/H22.33 H03/H22.31 H03/H22.29 H03/H22.27 H03/H22.25 H03/H22.23 H03/H22.21 H03/H22.19 H03/H22.17 H03/H22.15 H03/H22.13 H03/H22.11 H03/H22.9 H03/H22.7 H03/H22.5 H03/H22.3 H03/H22.1 73.66,74.93 76.2,72.39 E38.1 | E34.4 91.44,120.65 92.71,119.38 92.71,109.86 93.98,108.58 C38.2 | D5.A R29.1 | v149.86,46.35 E12.12 | C43.2 162.56,61.59 163.83,60.33 163.83,56.52 162.56,55.24 C47.2 | E39.7 93.98,21.59 92.71,22.86 92.71,33.02 93.98,34.29 E18.7 93.98,36.83 92.71,38.1 92.71,50.8 93.98,52.07 E17.7 | 128.91,74.3 132.08,77.47 E24.11 132.08,80.01 127,85.09 C30.2 | 128.91,74.3 127,72.39 E24.8 | 128.91,74.3 E24.10 132.08,60.33 127,55.24 C34.2 | 111.76,73.66 E24.19 | 111.76,73.66 E24.2 | E24.17 111.76,73.66 | C28.2 96.52,55.24 99.06,57.78 E38.10
  Bottom 0.635: E3.7 189.23,54.61 C8.2 | E6.7 189.23,36.83 C11.2 191.13,36.83 201.29,26.67 C49.- 199.39,24.77 194.31,24.77 191.13,21.59 C14.2 189.23,21.59 E9.7 186.06,22.23 173.35,22.23 | E12.7 161.29,36.83 C15.2 | E15.7 161.29,21.59 C20.2 162.56,22.23 173.35,22.23 | 173.35,22.23 E9.2 | 150.5,3.17 149.22,3.17 E4.1 | 150.5,3.17 E4.3 | 150.5,3.17 157.48,3.17 C18.2 165.74,6.35 168.91,9.53 C50.- | E20.4 158.75,107.95 C25.2 163.19,107.95 164.47,106.68 R18.2 E8.1 173.35,106.05 174.62,106.05 E8.2 177.16,108.58 190.5,108.58 C13.2 189.23,107.95 E8.7 | C26.2 158.75,123.19 E21.4 154.94,119.38 H05/H24.23 | C24.2 158.75,92.71 E19.4 154.94,93.98 H05/H24.3 | E35.4 219.71,36.83 C40.2 | E30.7 219.71,54.61 C35.2 | E11.7 189.23,92.71 C16.2 | E22.4 219.71,92.71 C27.2 | E7.7 219.71,107.95 C12.2 | C33.2 219.71,72.39 E28.7 215.9,68.58 D2.A 196.85,68.58 193.04,72.39 C36.2 189.23,72.39 E31.7 | C42.2 59.69,123.19 E37.4 55.88,119.38 H02/H21.23 | C41.2 59.69,107.95 E36.4 55.88,104.14 H02/H21.11 | C46.2 26.67,123.19 E41.4 22.86,119.38 H01/H20.23 | H01/H20.3 22.86,93.98 E40.4 26.67,92.71 C45.2 34.92,92.71 38.1,89.53 40.01,91.44 H02/H21.1 | C7.2 67.31,54.61 E2.7 63.5,50.8 C44.2 | E5.7 67.31,36.83 C10.2 | E1.10 31.11,71.75 31.75,71.75 32.38,72.39 C6.2 33.02,71.75 42.55,71.75 E14.1 | E10.20 33.66,43.81 38.73,43.81 E16.14 | E27.4 125.73,123.19 C32.2 | C31.2 125.73,107.95 E26.4 121.92,104.14 H04/H23.11 | E14.10 67.31,72.39 C9.2 74.93,72.39 E38.1 | E34.4 92.71,123.19 C39.2 | C38.2 92.71,107.95 E33.4 88.9,104.14 H03/H22.11 | H03/H22.3 88.9,93.98 E32.4 92.71,92.71 C37.2 94.61,92.71 97.79,89.53 104.14,89.53 106.05,91.44 H04/H23.1
  Bottom 0.635: E43.7 161.29,72.39 C43.2 | C47.2 161.29,54.61 E42.7 160.02,52.07 154.31,46.35 v149.86,46.35 147.96,48.26 R29.1 | E29.7 125.73,54.61 C34.2 127.64,54.61 131.44,50.8 D5.A | E18.7 95.25,36.83 C22.2 | E39.7 95.25,21.59 C23.2 96.52,22.23 128.27,22.23 128.91,21.59 C21.2 | E24.10 133.35,72.39 C29.2 | E25.4 125.09,92.08 125.73,92.08 126.36,92.71 C30.2 127.64,92.71 130.81,89.53 137.16,89.53 139.06,91.44 H05/H24.1 | E24.2 111.12,70.48 109.86,70.48 E24.1 107.95,72.39 C19.2 101.6,73.03 99.06,73.03 | C28.2 95.25,54.61 E17.7 88.9,48.26 R16.2 | 99.06,73.03 95.89,73.03 E38.8 | 99.06,73.03 E38.10 | E24.15 120.02,76.83 118.75,76.83 E24.17
  pour Top (isolate 0.254): 0,152.4 228.6,152.4 228.6,0 0,0
  pour Bottom (isolate 0.254): 0,152.4 228.6,152.4 228.6,0 0,0
N$1
  Top 0.254: PAD1.1 E7.5
N$2
  Top 0.254: E28.4 210.82,72.39 212.09,73.66 212.09,88.9 213.36,90.17 E22.2
N$3
  Top 0.254: PAD2.1 E7.6
N$4
  Top 0.254: E15.9 PAD3.1
N$5
  Top 0.254: E29.4 117.47,52.7 118.75,52.7 E29.5 119.38,52.07 121.92,49.53 C5.2 R29.2 D5.C
N$6
  Top 0.254: E15.8 PAD4.1
N$7
  Top 0.254: JP4.2 JP4.4 JP4.6
  Bottom 0.254: E8.13 179.07,110.49 217.17,110.49 219.71,113.03 219.71,125.73 215.26,125.73 214,127 JP4.4
N$8  (via drill 0.61)
  Top 0.254: E2.11 58.42,57.15 55.88,54.61 E2.3 55.88,52.07 57.15,50.8 57.15,45.72 58.42,44.45 E5.11 58.42,39.37 57.15,38.1 | 57.15,38.1 55.88,36.83 E5.3 | v60.33,23.5 57.15,26.67 57.15,38.1
  Bottom 0.254: v60.33,23.5 80.64,23.5 E39.3
N$9
  Top 0.254: R21.2 D2.C | E31.5 182.88,69.85 185.42,67.31 C2.2
  Bottom 0.254: E31.4 180.97,70.48 182.25,70.48 E31.5 | C2.2 R21.2
N$10
  Top 0.254: E35.7 213.36,44.45 212.09,45.72 212.09,55.88 208.28,59.69 E30.12
N$11
  Top 0.254: E38.11 PAD5.1
N$12  (via drill 0.61)
  Top 0.254: v72.39,38.1 76.2,41.91 76.2,66.04 80.01,69.85 v80.01,99.06
  Bottom 0.254: v72.39,38.1 66.04,38.1 E5.6 | v80.01,99.06 81.92,100.97 87,100.97 E32.6
N$13
  Top 0.254: E38.13 PAD6.1
N$14  (via drill 0.61)
  Top 0.254: v67.31,92.08 67.31,69.85 66.04,68.58 E2.8
  Bottom 0.254: v67.31,92.08 70.48,95.25 91.44,95.25 92.71,93.98 102.23,93.98 103.5,92.71 116.84,92.71 E25.1
N$15  (via drill 0.61)
  Top 0.254: v62.23,85.72 62.23,55.88 63.5,54.61 E2.6 | v120.02,87 123.19,90.17 123.19,96.52 121.92,97.79 E25.6
  Bottom 0.254: v62.23,85.72 63.5,87 v120.02,87
N$16
  Top 0.254: E17.11 86.36,57.15 83.82,54.61 E17.3 83.82,52.07 86.36,49.53 E18.11 86.36,39.37 83.82,36.83 E18.3 90.17,29.21 90.17,22.86 91.44,21.59 E39.6
N$17  (via drill 0.61)
  Top 0.254: v64.77,90.81 64.77,45.72 66.04,44.45 E5.8
  Bottom 0.254: v64.77,90.81 65.41,90.17 83.82,90.17 E32.1
N$18
  Top 0.254: E38.15 PAD7.1
N$19
  Top 0.254: E38.19 PAD9.1
N$20
  Top 0.254: C2.1 R22.1 E31.3
N$21  (via drill 0.61)
  Top 0.254: E43.10 154.94,77.47 156.21,76.2 156.21,63.5 154.94,62.23 E42.10 | E18.4 86.36,36.83 88.9,39.37 E18.10 88.9,44.45 87,46.35 87,52.7 E17.4 86.36,54.61 88.9,57.15 E17.10 | E5.4 58.42,36.83 60.96,39.37 E5.10 60.96,44.45 62.23,45.72 62.23,54.61 60.96,55.88 E2.10 | v54.61,58.42 54.61,62.23 53.98,62.87 53.98,69.22 53.34,69.85 E14.5
  Bottom 0.254: 152.4,57.78 152.4,59.05 153.03,59.05 E42.10 153.03,62.87 152.4,62.87 E43.4 | 152.4,57.78 E42.4 | 58.42,58.42 58.42,59.05 59.05,59.05 E2.10 | 58.42,58.42 58.42,55.88 | 58.42,55.88 E2.4 | 58.42,58.42 v54.61,58.42 | 58.42,55.88 83.82,55.88 E17.4 | 152.4,57.78 92.08,57.78 E17.10
N$22  (via drill 0.61)
  Top 0.254: v59.69,89.53 59.69,73.66 58.42,72.39 E14.7 | E32.2 E32.7 | E19.2 E19.7 E20.2 E20.7 | E25.2 E25.7 E26.2 E26.7 E27.2 E27.7
  Bottom 0.254: v59.69,89.53 84.45,89.53 E32.2 89.53,88.27 121.28,88.27 123.19,90.17 123.19,93.34 121.28,93.34 E25.2 | E20.2 150.5,108.58 140.97,108.58 140.34,107.95 128.91,107.95 127.64,109.22 121.92,109.22 E26.2
N$23  (via drill 0.61)
  Top 0.254: E31.2 v175.26,76.2
  Bottom 0.254: E31.2 177.16,69.22 183.51,69.22 E31.6 | v175.26,76.2 129.54,76.2 E24.13
N$24  (via drill 0.61)
  Top 0.254: v109.22,55.88 113.03,59.69 113.03,72.39 118.11,77.47 118.11,87.63 120.65,90.17 120.65,102.87 123.19,105.41 123.19,111.76 121.92,113.03 E26.6
  Bottom 0.254: v109.22,55.88 93.98,55.88 E17.6
N$25  (via drill 0.61)
  Top 0.254: v121.92,40.64 126.36,45.09 126.36,53.34 125.73,53.98 125.73,124.46 121.92,128.27 E27.6
  Bottom 0.254: v121.92,40.64 96.52,40.64 E18.6
N$26  (via drill 0.61)
  Top 0.254: v102.87,118.11 102.87,53.34 93.98,44.45 E18.8
  Bottom 0.254: v102.87,118.11 102.87,120.65 116.84,120.65 E27.1
N$27  (via drill 0.61)
  Top 0.254: v105.41,63.5 106.68,64.77 106.68,86.36 115.57,95.25 115.57,104.14 116.84,105.41 E26.1
  Bottom 0.254: v105.41,63.5 96.52,63.5 E17.8
N$28
  Top 0.254: PAD10.1 E38.9
N$29
  Top 0.254: E20.6 154.94,113.03 156.21,111.76 156.21,110.49 158.75,107.95 158.75,103.5 161.29,100.97 161.29,59.69 157.48,55.88 E42.6
N$30  (via drill 0.61)
  Top 0.254: v148.59,55.24 148.59,104.14 149.86,105.41 E20.1
  Bottom 0.254: v148.59,55.24 148.59,51.44 155.57,51.44 156.21,52.07 156.21,59.05 158.12,59.05 E42.8
N$31
  Top 0.254: E35.3 215.9,36.83 214.63,38.1 214.63,50.8 215.9,52.07 E30.6
  Bottom 0.254: E31.1 175.26,68.58 185.42,68.58 186.69,67.31 209.55,67.31 214.63,62.23 214.63,54.61 215.9,54.61 E30.6
N$32
  Top 0.254: PAD11.1 E38.7
N$33
  Top 0.254: C4.2 R27.2 D4.C E31.9
  Bottom 0.254: E31.10 183.51,78.11 184.78,78.11 E31.9
N$34
  Top 0.254: E31.11 C4.1
  Bottom 0.254: C4.1 R28.1
N$35
  Top 0.254: E30.1 203.2,52.07 209.55,45.72 209.55,38.1 210.82,36.83 E35.1
  Bottom 0.254: E3.12 179.71,62.87 188.59,62.87 189.23,62.23 189.23,55.88 200.66,55.88 E30.1
N$36
  Top 0.254: PAD16.1 E38.5
N$37
  Bottom 0.254: 173.35,80.64 168.91,85.09 161.29,85.09 161.29,77.47 160.66,76.83 146.05,76.83 146.05,80.01 145.41,80.64 139.7,80.64 138.43,81.92 115.57,81.92 115.57,77.47 116.84,76.2 118.11,76.2 118.11,73.66 116.84,72.39 E24.4 | E31.13 173.35,80.64 | 173.35,80.64 186.06,80.64 E31.8
N$38
  Top 0.254: E22.6 215.9,97.79 214.63,96.52 214.63,88.9 213.36,87.63 E28.10
  Bottom 0.254: E31.12 180.34,76.2 210.82,76.2 E28.10
N$39
  Top 0.254: C5.1 R30.1 E29.3
N$40
  Top 0.254: E24.6 121.92,69.85 120.65,68.58 120.65,55.88 121.92,54.61 E29.6
  Bottom 0.254: E29.2 113.67,51.44 120.02,51.44 E29.6
N$41  (via drill 0.61)
  Top 0.254: E43.11 152.4,74.93 149.86,72.39 E43.3 149.86,69.85 152.4,67.31 E42.11 152.4,59.69 149.86,57.15 E42.3 149.86,52.07 148.59,50.8 148.59,34.29 v147.32,33.02
  Bottom 0.254: v147.32,33.02 99.06,33.02 E39.8
N$42
  Top 0.254: PAD17.1 E38.3
N$43
  Top 0.254: E38.17 PAD8.1
N$44
  Top 0.254: PAD18.1 E44.1
N$45
  Top 0.254: PAD19.1 E44.2
N$46
  Top 0.254: PAD20.1 E44.3
N$47
  Top 0.254: PAD21.1 E44.4
N$48
  Top 0.254: E28.12 208.28,80.01 208.91,80.64 208.91,93.34 213.36,97.79 E22.7
N$49
  Top 0.254: E28.6 215.9,72.39 214.63,73.66 214.63,87.63 215.9,88.9 E22.3
N$50
  Top 0.254: E28.8 218.44,80.01 217.17,81.28 217.17,96.52 218.44,97.79 E22.5
N$51
  Top 0.254: E30.4 210.82,52.07 211.46,51.44 211.46,45.09 212.09,44.45 212.09,38.1 213.36,36.83 E35.2
N$52
  Bottom 0.254: E35.6 207.01,52.07 207.01,59.05 211.46,59.05 E30.10
N$53
  Top 0.254: E35.5 218.44,44.45 217.17,45.72 217.17,58.42 218.44,59.69 E30.8
N$54
  Top 0.254: E15.11 PAD12.1
N$55
  Top 0.254: E15.10 PAD13.1
N$56
  Top 0.254: E15.13 PAD14.1
N$57
  Top 0.254: E15.12 PAD15.1
N$58
  Top 0.254: PAD22.1 E44.5
N$59
  Top 0.254: PAD23.1 E44.6
N$60
  Top 0.254: PAD24.1 E44.7
N$61
  Top 0.254: PAD25.1 E44.8
N$62
  Top 0.254: E44.16 PAD26.1
N$63
  Top 0.254: E44.15 PAD37.1
N$64
  Top 0.254: E44.14 PAD38.1
N$65
  Top 0.254: E44.13 PAD39.1
N$66
  Top 0.254: E44.12 PAD40.1
N$67
  Top 0.254: E19.6 154.94,100.97 156.21,102.23 158.75,102.23 158.75,73.66 157.48,72.39 E43.6
N$68
  Bottom 0.254: E43.8 160.02,80.01 149.86,90.17 E19.1
N$69
  Top 0.254: E44.11 PAD41.1
N$70
  Top 0.254: E44.10 PAD45.1
N$71
  Top 0.254: PAD27.1 E3.3
N$72
  Top 0.254: PAD28.1 E3.4
N$73  (via drill 0.61)
  Top 0.254: v186.69,117.47 186.69,113.03 181.61,107.95 181.61,104.78 183.51,104.78 E8.6
  Bottom 0.254: v186.69,117.47 190.5,121.28 212.09,121.28 215.26,124.46 JP4.1
N$74
  Top 0.254: PAD29.1 E3.5
N$75
  Top 0.254: PAD30.1 E3.6
N$76
  Top 0.254: E29.9 PAD31.1
N$77
  Top 0.254: E29.10 PAD32.1
N$78
  Top 0.254: E29.8 PAD33.1
N$79
  Top 0.254: E29.12 PAD34.1
N$80
  Top 0.254: E29.13 PAD35.1
N$81
  Top 0.254: E29.11 PAD36.1
N$82
  Top 0.254: E44.9 PAD46.1
N$83
  Top 0.254: PAD47.1 E13.1
N$84
  Top 0.254: PAD48.1 E13.2
N$85
  Top 0.254: PAD49.1 E13.3
N$86
  Top 0.254: PAD50.1 E13.4
N$87
  Top 0.254: E39.12 PAD42.1
N$88
  Top 0.254: E39.13 PAD43.1
N$89
  Top 0.254: E39.11 PAD44.1
N$90
  Top 0.254: PAD51.1 E13.5
N$91
  Top 0.254: PAD52.1 E13.6
N$92
  Top 0.254: PAD53.1 E13.7
N$93
  Top 0.254: PAD54.1 E13.8
N$94  (via drill 0.61)
  Top 0.254: v165.74,55.88 165.74,59.69 163.83,61.59 163.83,132.08 152.4,132.08 151.13,130.81 151.13,124.46 149.86,123.19 E21.1
  Bottom 0.254: v165.74,55.88 167,57.15 184.15,57.15 E3.8
N$95
  Top 0.254: E13.16 PAD55.1
N$96
  Top 0.254: E13.15 PAD56.1
N$97
  Top 0.254: E13.14 PAD57.1
N$98
  Top 0.254: E13.13 PAD58.1
N$99
  Top 0.254: E13.12 PAD59.1
N$100
  Top 0.254: E13.11 PAD60.1
N$101
  Top 0.254: E13.10 PAD61.1
N$102
  Top 0.254: E13.9 PAD62.1
N$103
  Top 0.254: E7.2 212.09,113.03 212.09,121.28 214.63,123.83 214.63,125.09 215.9,126.36 JP4.3
N$108
  Top 0.254: E8.8 187.96,115.57 188.59,116.2 188.59,123.19 189.23,123.83 189.23,130.18 189.87,130.81 217.81,130.81 217.81,116.2 217.17,115.57 217.17,113.03 212.09,107.95 212.09,105.41 211.46,104.78 208.28,104.78 E7.3
N$111
  Top 0.254: E7.4 210.82,107.95 214.63,111.76 214.63,121.28 217.17,123.83 217.17,127.64 215.9,128.91 JP4.5
N$113  (via drill 0.61)
  Top 0.254: v191.77,100.97 200.66,109.86 JP3.2 JP3.4
  Bottom 0.254: v191.77,100.97 177.16,100.97 E11.13
N$128  (via drill 0.61)
  Top 0.254: JP2.2 JP2.4 JP2.6 175.9,129.54 169.54,123.19 169.54,94.61 v168.91,93.98
  Bottom 0.254: v168.91,93.98 172.72,93.98 E11.2
N$129  (via drill 0.61)
  Top 0.254: v170.18,92.71 170.18,118.75 175.26,123.83 JP1.2 JP1.4
  Bottom 0.254: v170.18,92.71 171.45,92.71 E11.1
N$132
  Top 0.254: E11.12 177.8,100.33 176.53,101.6 176.53,111.76 177.8,113.03 E8.12
VCC
  Top 0.635: E43.14 144.78,77.47 143.51,76.2 143.51,63.5 144.78,62.23 E42.14 144.78,59.69 143.51,58.42 143.51,40.64 | 171.45,80.01 168.28,83.19 168.28,83.82 R28.2 167.64,84.45 171.45,88.27 171.45,101.6 | 171.45,80.01 E31.14 | 171.45,80.01 171.45,70.48 167.64,66.67 R22.2 168.28,66.04 168.28,65.41 E3.14 172.72,59.69 171.45,58.42 171.45,40.64 | 171.45,40.64 171.45,30.48 172.72,29.21 E9.14 | 171.45,40.64 172.72,41.91 E6.14 | C18.1 157.48,12.06 161.29,15.88 161.29,24.77 162.56,26.04 C20.1 | 143.51,40.64 143.51,30.48 144.78,29.21 E15.14 | 143.51,40.64 144.78,41.91 E12.14 | 191.77,24.77 190.5,26.04 C14.1 | 191.77,24.77 191.77,10.79 C50.+ | 191.77,40.01 190.5,41.27 C11.1 | 191.77,40.01 191.77,24.77 | 191.77,40.01 191.77,57.78 190.5,59.05 C8.1 | 222.25,57.78 220.98,59.05 C35.1 | 222.25,57.78 222.25,43.81 220.98,42.55 C40.1 | 222.25,57.78 222.25,75.56 220.98,76.83 C33.1 | E19.8 149.86,100.33 151.13,101.6 151.13,111.76 149.86,113.03 E20.8 149.86,116.84 148.59,118.11 148.59,127 149.86,128.27 E21.8 | C12.1 220.98,112.39 222.25,111.12 222.25,99.69 220.98,98.42 C27.1 | C13.1 190.5,112.39 189.23,111.12 189.23,105.41 190.5,104.14 C16.1 | 171.45,101.6 171.45,111.76 172.72,113.03 E8.14 | 171.45,101.6 172.72,100.33 E11.14 | E10.28 7.62,39.37 8.89,40.64 8.89,58.42 7.62,59.69 E16.28 7.62,62.23 6.35,63.5 6.35,76.2 7.62,77.47 E1.20 | E37.8 50.8,128.27 49.53,127 49.53,116.84 50.8,115.57 E36.8 50.8,113.03 43.18,105.41 E14.20 43.18,77.47 41.91,76.2 41.91,57.78 43.18,56.52 C44.1 43.18,55.24 45.72,52.7 R15.1 45.72,36.2 44.45,34.92 | C6.1 33.02,78.11 31.75,79.38 31.75,93.34 27.94,97.16 C45.1
  Top 0.635: E41.8 17.78,128.27 19.05,127 19.05,101.6 17.78,100.33 E40.8 | 67.31,40.01 67.31,36.2 67.94,35.56 67.94,27.94 68.58,27.3 C17.1 | 67.31,40.01 68.58,41.27 C10.1 | 67.31,40.01 67.31,57.78 68.58,59.05 C7.1 68.58,60.33 69.85,61.59 69.85,73.66 68.58,74.93 C9.1 | VCC.1 46.99,8.89 46.99,9.53 C52.+ 45.09,11.43 44.45,12.06 44.45,34.92 | 44.45,34.92 43.18,33.66 C48.1 | 118.11,111.76 118.11,101.6 116.84,100.33 E25.8 116.84,93.98 109.22,86.36 E24.20 109.22,77.47 107.95,76.2 107.95,58.42 | 118.11,111.76 116.84,113.03 E26.8 | 118.11,111.76 118.11,127 116.84,128.27 E27.8 | 82.55,111.76 82.55,101.6 83.82,100.33 E32.8 | 82.55,111.76 83.82,113.03 E33.8 | 82.55,111.76 82.55,127 83.82,128.27 E34.8 | 95.25,24.77 96.52,26.04 C23.1 | 95.25,24.77 95.25,10.79 C51.+ | 95.25,24.77 95.25,40.01 96.52,41.27 C22.1 97.16,41.91 103.5,48.26 R30.2 104.14,54.61 107.95,58.42 | 107.95,58.42 109.22,59.69 E29.14 | C37.1 93.98,97.16 101.6,89.53 C19.1
  Bottom 0.635: C29.1 135.25,77.47 135.89,78.11 144.15,78.11 E43.14 | E42.14 144.15,60.33 128.27,60.33 127.64,59.69 C34.1 126.36,59.69 125.73,59.05 111.12,59.05 E29.14 108.58,60.33 97.79,60.33 97.16,59.69 C28.1 | C47.1 162.56,60.33 167.64,65.41 R22.2 | C43.1 162.56,78.11 167.64,83.19 R28.2 | C21.1 130.18,26.67 131.44,27.94 E15.14 | E4.2 156.21,11.43 C18.1 | C20.1 163.19,26.67 163.83,27.3 172.09,27.3 E9.14 | E12.14 146.69,41.27 162.56,41.27 C15.1 171.45,41.91 E6.14 | C8.1 191.13,59.69 191.77,60.33 202.56,60.33 E30.14 | 220.98,41.27 212.72,41.27 E35.8 210.19,42.55 191.77,42.55 191.13,41.91 C11.1 | 220.98,41.27 222.88,41.27 222.88,26.67 C49.+ | C40.1 220.98,41.27 | R17.1 161.93,129.54 160.66,128.27 C26.1 160.02,127.64 151.76,127.64 E21.8 | E8.14 172.09,113.67 161.29,113.67 160.66,113.03 C25.1 159.38,113.03 158.75,112.39 151.76,112.39 E20.8 | C13.1 191.13,113.03 191.77,113.67 202.56,113.67 E7.14 | C36.1 191.13,77.47 191.77,78.11 202.56,78.11 E28.14 203.2,80.64 | C24.1 160.66,97.79 161.29,98.42 172.09,98.42 E11.14 174.62,97.16 190.5,97.16 C16.1 191.13,97.79 191.77,98.42 203.2,98.42 | 203.2,98.42 210.19,98.42 E22.8 212.72,97.16 219.71,97.16 220.34,97.79 C27.1 | 203.2,98.42 203.2,80.64 | 203.2,80.64 220.98,80.64 C33.1 | C41.1 60.33,113.03 59.69,112.39 52.7,112.39 E36.8 | C42.1 60.33,128.27 59.69,127.64 52.7,127.64 E37.8 | C46.1 27.3,128.27 26.67,127.64 19.68,127.64 E41.8 | E14.20 43.18,77.47 C6.1 33.02,76.83 9.53,76.83 E1.20 | C45.1 27.94,100.97 19.68,100.97 E40.8 | C7.1 69.22,59.69 69.85,60.33 78.11,60.33 E17.14 | C17.1 69.22,26.67 69.85,27.3 78.11,27.3 E39.14 | E18.14 70.48,43.18 69.22,41.91 C10.1 68.58,45.09 48.9,45.09
  Bottom 0.635: 48.9,45.09 46.35,47.62 45.72,47.62 R15.1 | 48.9,45.09 E5.14 | E2.14 50.8,59.69 46.99,55.88 C44.1 | C32.1 127,131.44 118.75,131.44 E27.8 | C30.1 126.36,97.79 125.73,97.16 118.75,97.16 E25.8 | C31.1 126.36,113.03 125.73,112.39 118.75,112.39 E26.8 | C39.1 93.98,131.44 85.72,131.44 E34.8 | C37.1 93.34,97.79 92.71,97.16 85.72,97.16 E32.8 | C38.1 93.34,113.03 92.71,112.39 85.72,112.39 E33.8 | C9.1 69.22,77.47 69.85,78.11 75.56,78.11 E38.20 78.11,76.83 101.6,76.83 C19.1 102.23,77.47 102.87,78.11 108.58,78.11 E24.20

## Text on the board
Top: PDP-8/i RAM Memory | VRS
Bottom: PDP-8/i RAM Memory | VRS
